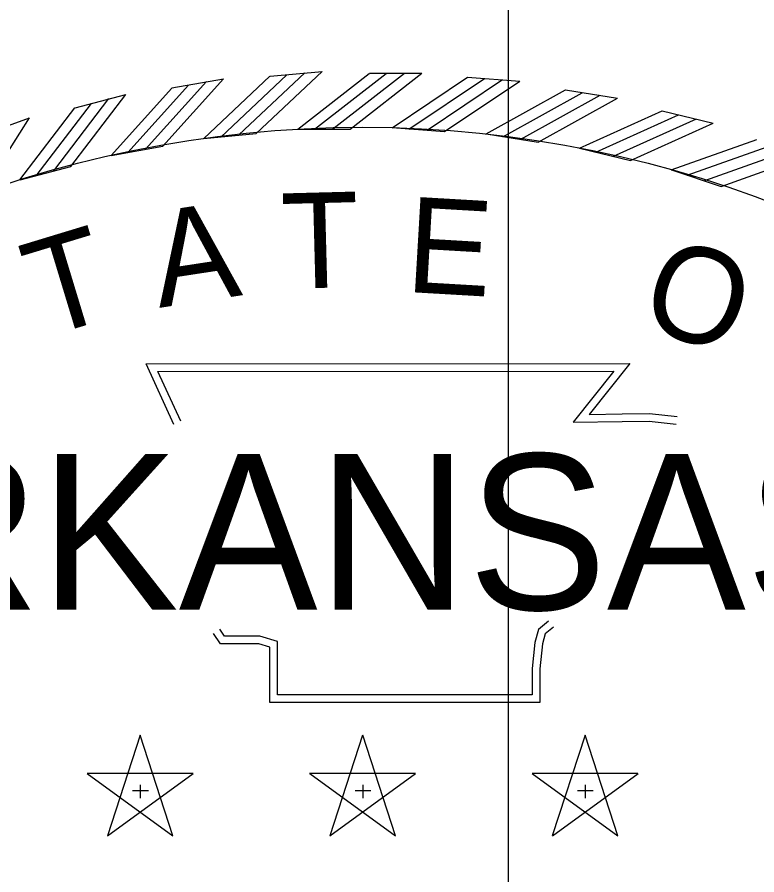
# Model space of a CAD drawing. Extents: x 18 to 14744716, y -5 to 1829144.
# Drawn here: x 17.7416 to 17.7948, y 10.9344 to 10.9961 of the extents above; entities that cross this region are included whole.
import ezdxf

# ---------------------------------------------------------------- set-up
doc = ezdxf.new("R2010")
doc.units = 0
for name, color, linetype in [('B_StampERBB', 7, 'Continuous'), ('B_StampHSS', 7, 'Continuous'), ('B_StampJSB', 7, 'Continuous'), ('B_StampSCR', 7, 'Continuous'), ('B_StampSFH', 7, 'Continuous'), ('R_No Plot', 7, 'Continuous')]:
    doc.layers.add(name, color=color, linetype=linetype)

msp = doc.modelspace()

# ---------------------------------------------------------------- linework, layer by layer
at = {"layer": 'B_StampERBB'}
for p, q in [((17.759782, 10.99184), (17.763536, 10.992186)), ((17.766921, 10.99205), (17.770691, 10.99205)), ((17.752726, 10.990997), (17.756438, 10.991651)), ((17.773983, 10.991767), (17.777742, 10.991491)), ((17.78103, 10.990852), (17.784754, 10.990266)), ((17.745763, 10.989574), (17.749409, 10.990533)), ((17.787978, 10.989358), (17.791641, 10.988467)), ((17.738942, 10.987581), (17.742496, 10.988838)), ((17.755027, 10.987373), (17.75879, 10.98772)), ((17.761776, 10.988038), (17.765555, 10.988038)), ((17.768557, 10.988144), (17.772326, 10.987867)), ((17.775324, 10.987689), (17.779057, 10.987102)), ((17.748356, 10.986153), (17.752077, 10.986809)), ((17.78203, 10.986678), (17.785702, 10.985784)), ((17.741808, 10.984385), (17.745463, 10.985347)), ((17.78863, 10.985115), (17.792215, 10.983921)), ((17.750447, 10.944483), (17.748088, 10.937247)), ((17.752797, 10.937251), (17.750452, 10.944492)), ((17.766438, 10.944483), (17.764079, 10.937247)), ((17.768788, 10.937251), (17.766443, 10.944492)), ((17.782429, 10.944483), (17.78007, 10.937247)), ((17.784779, 10.937251), (17.782434, 10.944492)), ((17.754249, 10.941721), (17.746638, 10.941728)), ((17.746645, 10.941721), (17.752798, 10.937242)), ((17.748097, 10.937251), (17.754258, 10.941719)), ((17.77024, 10.941721), (17.762629, 10.941728)), ((17.762636, 10.941721), (17.768789, 10.937242)), ((17.764088, 10.937251), (17.770249, 10.941719)), ((17.786231, 10.941721), (17.77862, 10.941728)), ((17.778627, 10.941721), (17.78478, 10.937242)), ((17.780079, 10.937251), (17.786241, 10.941719)), ((17.750454, 10.940912), (17.750454, 10.939957)), ((17.766445, 10.940912), (17.766445, 10.939957)), ((17.782436, 10.940912), (17.782436, 10.939957)), ((17.749905, 10.940505), (17.751036, 10.940505)), ((17.765896, 10.940505), (17.767027, 10.940505)), ((17.781887, 10.940505), (17.783018, 10.940505))]:
    msp.add_line(p, q, dxfattribs=at)
for points in [[(17.757534, 10.987618), (17.762288, 10.992085)], [(17.758785, 10.987722), (17.763539, 10.992189)], [(17.761772, 10.988035), (17.766915, 10.992046)], [(17.762985, 10.988024), (17.768129, 10.992035)], [(17.764295, 10.988053), (17.769438, 10.992064)], [(17.765551, 10.988041), (17.770694, 10.992053)], [(17.750833, 10.986604), (17.755202, 10.991448)], [(17.752072, 10.986811), (17.756441, 10.991655)], [(17.755023, 10.987369), (17.759777, 10.991836)], [(17.756232, 10.987469), (17.760986, 10.991936)], [(17.768553, 10.988141), (17.773977, 10.991764)], [(17.769762, 10.988041), (17.775186, 10.991664)], [(17.77107, 10.987973), (17.776494, 10.991597)], [(17.772322, 10.98787), (17.777746, 10.991493)], [(17.748352, 10.986148), (17.752721, 10.990992)], [(17.749549, 10.986348), (17.753918, 10.991192)], [(17.775319, 10.987687), (17.781024, 10.99085)], [(17.74424, 10.98504), (17.748194, 10.990228)], [(17.745458, 10.985348), (17.749412, 10.990536)], [(17.776516, 10.987487), (17.782221, 10.99065)], [(17.777814, 10.987312), (17.783519, 10.990475)], [(17.779053, 10.987105), (17.784758, 10.990268)], [(17.741805, 10.984381), (17.745759, 10.989569)], [(17.742981, 10.984679), (17.746935, 10.989867)], [(17.782025, 10.986675), (17.787972, 10.989356)], [(17.783201, 10.986377), (17.789148, 10.989058)], [(17.738986, 10.983344), (17.742498, 10.988841)], [(17.78448, 10.986096), (17.790427, 10.988777)], [(17.785698, 10.985787), (17.791645, 10.988468)], [(17.788624, 10.985113), (17.794772, 10.987294)], [(17.789772, 10.984719), (17.79592, 10.9869)], [(17.791024, 10.984333), (17.797171, 10.986514)], [(17.792211, 10.983925), (17.798359, 10.986106)], [(17.752875, 10.966818), (17.750865, 10.97117), (17.785635, 10.97119), (17.78273, 10.96754), (17.785092, 10.967571), (17.787065, 10.967597), (17.789037, 10.967382)], [(17.753375, 10.967049), (17.751726, 10.97062), (17.784493, 10.970639), (17.781576, 10.966974), (17.785099, 10.96702), (17.787039, 10.967045), (17.788977, 10.966834)], [(17.779808, 10.952675), (17.779078, 10.95208), (17.778824, 10.951147), (17.778619, 10.949271), (17.778619, 10.947388), (17.760311, 10.947388), (17.760311, 10.950082), (17.760311, 10.951211), (17.759055, 10.951594), (17.756509, 10.951594), (17.756182, 10.952094)], [(17.780156, 10.952247), (17.779563, 10.951765), (17.779366, 10.951044), (17.77917, 10.949241), (17.77917, 10.946838), (17.75976, 10.946838), (17.75976, 10.950082), (17.75976, 10.950803), (17.758973, 10.951044), (17.756212, 10.951044), (17.755721, 10.951792)]]:
    msp.add_lwpolyline(points, dxfattribs=at)
at = {"layer": 'B_StampHSS'}
for p, q in [((17.759782, 10.99184), (17.763536, 10.992186)), ((17.766921, 10.99205), (17.770691, 10.99205)), ((17.752726, 10.990997), (17.756438, 10.991651)), ((17.773983, 10.991767), (17.777742, 10.991491)), ((17.78103, 10.990852), (17.784754, 10.990266)), ((17.745763, 10.989574), (17.749409, 10.990533)), ((17.787978, 10.989358), (17.791641, 10.988467)), ((17.738942, 10.987581), (17.742496, 10.988838)), ((17.755027, 10.987373), (17.75879, 10.98772)), ((17.761776, 10.988038), (17.765555, 10.988038)), ((17.768557, 10.988144), (17.772326, 10.987867)), ((17.775324, 10.987689), (17.779057, 10.987102)), ((17.748356, 10.986153), (17.752077, 10.986809)), ((17.78203, 10.986678), (17.785702, 10.985784)), ((17.741808, 10.984385), (17.745463, 10.985347)), ((17.78863, 10.985115), (17.792215, 10.983921)), ((17.750447, 10.944483), (17.748088, 10.937247)), ((17.752797, 10.937251), (17.750452, 10.944492)), ((17.766438, 10.944483), (17.764079, 10.937247)), ((17.768788, 10.937251), (17.766443, 10.944492)), ((17.782429, 10.944483), (17.78007, 10.937247)), ((17.784779, 10.937251), (17.782434, 10.944492)), ((17.754249, 10.941721), (17.746638, 10.941728)), ((17.746645, 10.941721), (17.752798, 10.937242)), ((17.748097, 10.937251), (17.754258, 10.941719)), ((17.77024, 10.941721), (17.762629, 10.941728)), ((17.762636, 10.941721), (17.768789, 10.937242)), ((17.764088, 10.937251), (17.770249, 10.941719)), ((17.786231, 10.941721), (17.77862, 10.941728)), ((17.778627, 10.941721), (17.78478, 10.937242)), ((17.780079, 10.937251), (17.786241, 10.941719)), ((17.750454, 10.940912), (17.750454, 10.939957)), ((17.766445, 10.940912), (17.766445, 10.939957)), ((17.782436, 10.940912), (17.782436, 10.939957)), ((17.749905, 10.940505), (17.751036, 10.940505)), ((17.765896, 10.940505), (17.767027, 10.940505)), ((17.781887, 10.940505), (17.783018, 10.940505))]:
    msp.add_line(p, q, dxfattribs=at)
for points in [[(17.757534, 10.987618), (17.762288, 10.992085)], [(17.758785, 10.987722), (17.763539, 10.992189)], [(17.761772, 10.988035), (17.766915, 10.992046)], [(17.762985, 10.988024), (17.768129, 10.992035)], [(17.764295, 10.988053), (17.769438, 10.992064)], [(17.765551, 10.988041), (17.770694, 10.992053)], [(17.750833, 10.986604), (17.755202, 10.991448)], [(17.752072, 10.986811), (17.756441, 10.991655)], [(17.755023, 10.987369), (17.759777, 10.991836)], [(17.756232, 10.987469), (17.760986, 10.991936)], [(17.768553, 10.988141), (17.773977, 10.991764)], [(17.769762, 10.988041), (17.775186, 10.991664)], [(17.77107, 10.987973), (17.776494, 10.991597)], [(17.772322, 10.98787), (17.777746, 10.991493)], [(17.748352, 10.986148), (17.752721, 10.990992)], [(17.749549, 10.986348), (17.753918, 10.991192)], [(17.775319, 10.987687), (17.781024, 10.99085)], [(17.74424, 10.98504), (17.748194, 10.990228)], [(17.745458, 10.985348), (17.749412, 10.990536)], [(17.776516, 10.987487), (17.782221, 10.99065)], [(17.777814, 10.987312), (17.783519, 10.990475)], [(17.779053, 10.987105), (17.784758, 10.990268)], [(17.741805, 10.984381), (17.745759, 10.989569)], [(17.742981, 10.984679), (17.746935, 10.989867)], [(17.782025, 10.986675), (17.787972, 10.989356)], [(17.783201, 10.986377), (17.789148, 10.989058)], [(17.738986, 10.983344), (17.742498, 10.988841)], [(17.78448, 10.986096), (17.790427, 10.988777)], [(17.785698, 10.985787), (17.791645, 10.988468)], [(17.788624, 10.985113), (17.794772, 10.987294)], [(17.789772, 10.984719), (17.79592, 10.9869)], [(17.791024, 10.984333), (17.797171, 10.986514)], [(17.792211, 10.983925), (17.798359, 10.986106)], [(17.752875, 10.966818), (17.750865, 10.97117), (17.785635, 10.97119), (17.78273, 10.96754), (17.785092, 10.967571), (17.787065, 10.967597), (17.789037, 10.967382)], [(17.753375, 10.967049), (17.751726, 10.97062), (17.784493, 10.970639), (17.781576, 10.966974), (17.785099, 10.96702), (17.787039, 10.967045), (17.788977, 10.966834)], [(17.779808, 10.952675), (17.779078, 10.95208), (17.778824, 10.951147), (17.778619, 10.949271), (17.778619, 10.947388), (17.760311, 10.947388), (17.760311, 10.950082), (17.760311, 10.951211), (17.759055, 10.951594), (17.756509, 10.951594), (17.756182, 10.952094)], [(17.780156, 10.952247), (17.779563, 10.951765), (17.779366, 10.951044), (17.77917, 10.949241), (17.77917, 10.946838), (17.75976, 10.946838), (17.75976, 10.950082), (17.75976, 10.950803), (17.758973, 10.951044), (17.756212, 10.951044), (17.755721, 10.951792)]]:
    msp.add_lwpolyline(points, dxfattribs=at)
at = {"layer": 'B_StampJSB'}
for p, q in [((17.759782, 10.99184), (17.763536, 10.992186)), ((17.766921, 10.99205), (17.770691, 10.99205)), ((17.752726, 10.990997), (17.756438, 10.991651)), ((17.773983, 10.991767), (17.777742, 10.991491)), ((17.78103, 10.990852), (17.784754, 10.990266)), ((17.745763, 10.989574), (17.749409, 10.990533)), ((17.787978, 10.989358), (17.791641, 10.988467)), ((17.738942, 10.987581), (17.742496, 10.988838)), ((17.755027, 10.987373), (17.75879, 10.98772)), ((17.761776, 10.988038), (17.765555, 10.988038)), ((17.768557, 10.988144), (17.772326, 10.987867)), ((17.775324, 10.987689), (17.779057, 10.987102)), ((17.748356, 10.986153), (17.752077, 10.986809)), ((17.78203, 10.986678), (17.785702, 10.985784)), ((17.741808, 10.984385), (17.745463, 10.985347)), ((17.78863, 10.985115), (17.792215, 10.983921)), ((17.750447, 10.944483), (17.748088, 10.937247)), ((17.752797, 10.937251), (17.750452, 10.944492)), ((17.766438, 10.944483), (17.764079, 10.937247)), ((17.768788, 10.937251), (17.766443, 10.944492)), ((17.782429, 10.944483), (17.78007, 10.937247)), ((17.784779, 10.937251), (17.782434, 10.944492)), ((17.754249, 10.941721), (17.746638, 10.941728)), ((17.746645, 10.941721), (17.752798, 10.937242)), ((17.748097, 10.937251), (17.754258, 10.941719)), ((17.77024, 10.941721), (17.762629, 10.941728)), ((17.762636, 10.941721), (17.768789, 10.937242)), ((17.764088, 10.937251), (17.770249, 10.941719)), ((17.786231, 10.941721), (17.77862, 10.941728)), ((17.778627, 10.941721), (17.78478, 10.937242)), ((17.780079, 10.937251), (17.786241, 10.941719)), ((17.750454, 10.940912), (17.750454, 10.939957)), ((17.766445, 10.940912), (17.766445, 10.939957)), ((17.782436, 10.940912), (17.782436, 10.939957)), ((17.749905, 10.940505), (17.751036, 10.940505)), ((17.765896, 10.940505), (17.767027, 10.940505)), ((17.781887, 10.940505), (17.783018, 10.940505))]:
    msp.add_line(p, q, dxfattribs=at)
for points in [[(17.757534, 10.987618), (17.762288, 10.992085)], [(17.758785, 10.987722), (17.763539, 10.992189)], [(17.761772, 10.988035), (17.766915, 10.992046)], [(17.762985, 10.988024), (17.768129, 10.992035)], [(17.764295, 10.988053), (17.769438, 10.992064)], [(17.765551, 10.988041), (17.770694, 10.992053)], [(17.750833, 10.986604), (17.755202, 10.991448)], [(17.752072, 10.986811), (17.756441, 10.991655)], [(17.755023, 10.987369), (17.759777, 10.991836)], [(17.756232, 10.987469), (17.760986, 10.991936)], [(17.768553, 10.988141), (17.773977, 10.991764)], [(17.769762, 10.988041), (17.775186, 10.991664)], [(17.77107, 10.987973), (17.776494, 10.991597)], [(17.772322, 10.98787), (17.777746, 10.991493)], [(17.748352, 10.986148), (17.752721, 10.990992)], [(17.749549, 10.986348), (17.753918, 10.991192)], [(17.775319, 10.987687), (17.781024, 10.99085)], [(17.74424, 10.98504), (17.748194, 10.990228)], [(17.745458, 10.985348), (17.749412, 10.990536)], [(17.776516, 10.987487), (17.782221, 10.99065)], [(17.777814, 10.987312), (17.783519, 10.990475)], [(17.779053, 10.987105), (17.784758, 10.990268)], [(17.741805, 10.984381), (17.745759, 10.989569)], [(17.742981, 10.984679), (17.746935, 10.989867)], [(17.782025, 10.986675), (17.787972, 10.989356)], [(17.783201, 10.986377), (17.789148, 10.989058)], [(17.738986, 10.983344), (17.742498, 10.988841)], [(17.78448, 10.986096), (17.790427, 10.988777)], [(17.785698, 10.985787), (17.791645, 10.988468)], [(17.788624, 10.985113), (17.794772, 10.987294)], [(17.789772, 10.984719), (17.79592, 10.9869)], [(17.791024, 10.984333), (17.797171, 10.986514)], [(17.792211, 10.983925), (17.798359, 10.986106)], [(17.752875, 10.966818), (17.750865, 10.97117), (17.785635, 10.97119), (17.78273, 10.96754), (17.785092, 10.967571), (17.787065, 10.967597), (17.789037, 10.967382)], [(17.753375, 10.967049), (17.751726, 10.97062), (17.784493, 10.970639), (17.781576, 10.966974), (17.785099, 10.96702), (17.787039, 10.967045), (17.788977, 10.966834)], [(17.779808, 10.952675), (17.779078, 10.95208), (17.778824, 10.951147), (17.778619, 10.949271), (17.778619, 10.947388), (17.760311, 10.947388), (17.760311, 10.950082), (17.760311, 10.951211), (17.759055, 10.951594), (17.756509, 10.951594), (17.756182, 10.952094)], [(17.780156, 10.952247), (17.779563, 10.951765), (17.779366, 10.951044), (17.77917, 10.949241), (17.77917, 10.946838), (17.75976, 10.946838), (17.75976, 10.950082), (17.75976, 10.950803), (17.758973, 10.951044), (17.756212, 10.951044), (17.755721, 10.951792)]]:
    msp.add_lwpolyline(points, dxfattribs=at)
msp.add_circle((17.766447, 10.906117), 0.082054, dxfattribs=at)
at = {"layer": 'B_StampSCR'}
for p, q in [((17.759782, 10.99184), (17.763536, 10.992186)), ((17.766921, 10.99205), (17.770691, 10.99205)), ((17.752726, 10.990997), (17.756438, 10.991651)), ((17.773983, 10.991767), (17.777742, 10.991491)), ((17.78103, 10.990852), (17.784754, 10.990266)), ((17.745763, 10.989574), (17.749409, 10.990533)), ((17.787978, 10.989358), (17.791641, 10.988467)), ((17.738942, 10.987581), (17.742496, 10.988838)), ((17.755027, 10.987373), (17.75879, 10.98772)), ((17.761776, 10.988038), (17.765555, 10.988038)), ((17.768557, 10.988144), (17.772326, 10.987867)), ((17.775324, 10.987689), (17.779057, 10.987102)), ((17.748356, 10.986153), (17.752077, 10.986809)), ((17.78203, 10.986678), (17.785702, 10.985784)), ((17.741808, 10.984385), (17.745463, 10.985347)), ((17.78863, 10.985115), (17.792215, 10.983921)), ((17.750447, 10.944483), (17.748088, 10.937247)), ((17.752797, 10.937251), (17.750452, 10.944492)), ((17.766438, 10.944483), (17.764079, 10.937247)), ((17.768788, 10.937251), (17.766443, 10.944492)), ((17.782429, 10.944483), (17.78007, 10.937247)), ((17.784779, 10.937251), (17.782434, 10.944492)), ((17.754249, 10.941721), (17.746638, 10.941728)), ((17.746645, 10.941721), (17.752798, 10.937242)), ((17.748097, 10.937251), (17.754258, 10.941719)), ((17.77024, 10.941721), (17.762629, 10.941728)), ((17.762636, 10.941721), (17.768789, 10.937242)), ((17.764088, 10.937251), (17.770249, 10.941719)), ((17.786231, 10.941721), (17.77862, 10.941728)), ((17.778627, 10.941721), (17.78478, 10.937242)), ((17.780079, 10.937251), (17.786241, 10.941719)), ((17.750454, 10.940912), (17.750454, 10.939957)), ((17.766445, 10.940912), (17.766445, 10.939957)), ((17.782436, 10.940912), (17.782436, 10.939957)), ((17.749905, 10.940505), (17.751036, 10.940505)), ((17.765896, 10.940505), (17.767027, 10.940505)), ((17.781887, 10.940505), (17.783018, 10.940505))]:
    msp.add_line(p, q, dxfattribs=at)
for points in [[(17.757534, 10.987618), (17.762288, 10.992085)], [(17.758785, 10.987722), (17.763539, 10.992189)], [(17.761772, 10.988035), (17.766915, 10.992046)], [(17.762985, 10.988024), (17.768129, 10.992035)], [(17.764295, 10.988053), (17.769438, 10.992064)], [(17.765551, 10.988041), (17.770694, 10.992053)], [(17.750833, 10.986604), (17.755202, 10.991448)], [(17.752072, 10.986811), (17.756441, 10.991655)], [(17.755023, 10.987369), (17.759777, 10.991836)], [(17.756232, 10.987469), (17.760986, 10.991936)], [(17.768553, 10.988141), (17.773977, 10.991764)], [(17.769762, 10.988041), (17.775186, 10.991664)], [(17.77107, 10.987973), (17.776494, 10.991597)], [(17.772322, 10.98787), (17.777746, 10.991493)], [(17.748352, 10.986148), (17.752721, 10.990992)], [(17.749549, 10.986348), (17.753918, 10.991192)], [(17.775319, 10.987687), (17.781024, 10.99085)], [(17.74424, 10.98504), (17.748194, 10.990228)], [(17.745458, 10.985348), (17.749412, 10.990536)], [(17.776516, 10.987487), (17.782221, 10.99065)], [(17.777814, 10.987312), (17.783519, 10.990475)], [(17.779053, 10.987105), (17.784758, 10.990268)], [(17.741805, 10.984381), (17.745759, 10.989569)], [(17.742981, 10.984679), (17.746935, 10.989867)], [(17.782025, 10.986675), (17.787972, 10.989356)], [(17.783201, 10.986377), (17.789148, 10.989058)], [(17.738986, 10.983344), (17.742498, 10.988841)], [(17.78448, 10.986096), (17.790427, 10.988777)], [(17.785698, 10.985787), (17.791645, 10.988468)], [(17.788624, 10.985113), (17.794772, 10.987294)], [(17.789772, 10.984719), (17.79592, 10.9869)], [(17.791024, 10.984333), (17.797171, 10.986514)], [(17.792211, 10.983925), (17.798359, 10.986106)], [(17.752875, 10.966818), (17.750865, 10.97117), (17.785635, 10.97119), (17.78273, 10.96754), (17.785092, 10.967571), (17.787065, 10.967597), (17.789037, 10.967382)], [(17.753375, 10.967049), (17.751726, 10.97062), (17.784493, 10.970639), (17.781576, 10.966974), (17.785099, 10.96702), (17.787039, 10.967045), (17.788977, 10.966834)], [(17.779808, 10.952675), (17.779078, 10.95208), (17.778824, 10.951147), (17.778619, 10.949271), (17.778619, 10.947388), (17.760311, 10.947388), (17.760311, 10.950082), (17.760311, 10.951211), (17.759055, 10.951594), (17.756509, 10.951594), (17.756182, 10.952094)], [(17.780156, 10.952247), (17.779563, 10.951765), (17.779366, 10.951044), (17.77917, 10.949241), (17.77917, 10.946838), (17.75976, 10.946838), (17.75976, 10.950082), (17.75976, 10.950803), (17.758973, 10.951044), (17.756212, 10.951044), (17.755721, 10.951792)]]:
    msp.add_lwpolyline(points, dxfattribs=at)
at = {"layer": 'B_StampSFH'}
for p, q in [((17.759782, 10.99184), (17.763536, 10.992186)), ((17.766921, 10.99205), (17.770691, 10.99205)), ((17.752726, 10.990997), (17.756438, 10.991651)), ((17.773983, 10.991767), (17.777742, 10.991491)), ((17.78103, 10.990852), (17.784754, 10.990266)), ((17.745763, 10.989574), (17.749409, 10.990533)), ((17.787978, 10.989358), (17.791641, 10.988467)), ((17.738942, 10.987581), (17.742496, 10.988838)), ((17.755027, 10.987373), (17.75879, 10.98772)), ((17.761776, 10.988038), (17.765555, 10.988038)), ((17.768557, 10.988144), (17.772326, 10.987867)), ((17.775324, 10.987689), (17.779057, 10.987102)), ((17.748356, 10.986153), (17.752077, 10.986809)), ((17.78203, 10.986678), (17.785702, 10.985784)), ((17.741808, 10.984385), (17.745463, 10.985347)), ((17.78863, 10.985115), (17.792215, 10.983921)), ((17.750447, 10.944483), (17.748088, 10.937247)), ((17.752797, 10.937251), (17.750452, 10.944492)), ((17.766438, 10.944483), (17.764079, 10.937247)), ((17.768788, 10.937251), (17.766443, 10.944492)), ((17.782429, 10.944483), (17.78007, 10.937247)), ((17.784779, 10.937251), (17.782434, 10.944492)), ((17.754249, 10.941721), (17.746638, 10.941728)), ((17.746645, 10.941721), (17.752798, 10.937242)), ((17.748097, 10.937251), (17.754258, 10.941719)), ((17.77024, 10.941721), (17.762629, 10.941728)), ((17.762636, 10.941721), (17.768789, 10.937242)), ((17.764088, 10.937251), (17.770249, 10.941719)), ((17.786231, 10.941721), (17.77862, 10.941728)), ((17.778627, 10.941721), (17.78478, 10.937242)), ((17.780079, 10.937251), (17.786241, 10.941719)), ((17.750454, 10.940912), (17.750454, 10.939957)), ((17.766445, 10.940912), (17.766445, 10.939957)), ((17.782436, 10.940912), (17.782436, 10.939957)), ((17.749905, 10.940505), (17.751036, 10.940505)), ((17.765896, 10.940505), (17.767027, 10.940505)), ((17.781887, 10.940505), (17.783018, 10.940505))]:
    msp.add_line(p, q, dxfattribs=at)
for points in [[(17.757534, 10.987618), (17.762288, 10.992085)], [(17.758785, 10.987722), (17.763539, 10.992189)], [(17.761772, 10.988035), (17.766915, 10.992046)], [(17.762985, 10.988024), (17.768129, 10.992035)], [(17.764295, 10.988053), (17.769438, 10.992064)], [(17.765551, 10.988041), (17.770694, 10.992053)], [(17.750833, 10.986604), (17.755202, 10.991448)], [(17.752072, 10.986811), (17.756441, 10.991655)], [(17.755023, 10.987369), (17.759777, 10.991836)], [(17.756232, 10.987469), (17.760986, 10.991936)], [(17.768553, 10.988141), (17.773977, 10.991764)], [(17.769762, 10.988041), (17.775186, 10.991664)], [(17.77107, 10.987973), (17.776494, 10.991597)], [(17.772322, 10.98787), (17.777746, 10.991493)], [(17.748352, 10.986148), (17.752721, 10.990992)], [(17.749549, 10.986348), (17.753918, 10.991192)], [(17.775319, 10.987687), (17.781024, 10.99085)], [(17.74424, 10.98504), (17.748194, 10.990228)], [(17.745458, 10.985348), (17.749412, 10.990536)], [(17.776516, 10.987487), (17.782221, 10.99065)], [(17.777814, 10.987312), (17.783519, 10.990475)], [(17.779053, 10.987105), (17.784758, 10.990268)], [(17.741805, 10.984381), (17.745759, 10.989569)], [(17.742981, 10.984679), (17.746935, 10.989867)], [(17.782025, 10.986675), (17.787972, 10.989356)], [(17.783201, 10.986377), (17.789148, 10.989058)], [(17.738986, 10.983344), (17.742498, 10.988841)], [(17.78448, 10.986096), (17.790427, 10.988777)], [(17.785698, 10.985787), (17.791645, 10.988468)], [(17.788624, 10.985113), (17.794772, 10.987294)], [(17.789772, 10.984719), (17.79592, 10.9869)], [(17.791024, 10.984333), (17.797171, 10.986514)], [(17.792211, 10.983925), (17.798359, 10.986106)], [(17.752875, 10.966818), (17.750865, 10.97117), (17.785635, 10.97119), (17.78273, 10.96754), (17.785092, 10.967571), (17.787065, 10.967597), (17.789037, 10.967382)], [(17.753375, 10.967049), (17.751726, 10.97062), (17.784493, 10.970639), (17.781576, 10.966974), (17.785099, 10.96702), (17.787039, 10.967045), (17.788977, 10.966834)], [(17.779808, 10.952675), (17.779078, 10.95208), (17.778824, 10.951147), (17.778619, 10.949271), (17.778619, 10.947388), (17.760311, 10.947388), (17.760311, 10.950082), (17.760311, 10.951211), (17.759055, 10.951594), (17.756509, 10.951594), (17.756182, 10.952094)], [(17.780156, 10.952247), (17.779563, 10.951765), (17.779366, 10.951044), (17.77917, 10.949241), (17.77917, 10.946838), (17.75976, 10.946838), (17.75976, 10.950082), (17.75976, 10.950803), (17.758973, 10.951044), (17.756212, 10.951044), (17.755721, 10.951792)]]:
    msp.add_lwpolyline(points, dxfattribs=at)
at = {"layer": 'R_No Plot'}
msp.add_lwpolyline([(17.776919, 16.627613), (51.776919, 16.627613), (51.776919, -5.372387), (17.776919, -5.372387)], close=True, dxfattribs=at)

# ---------------------------------------------------------------- texts
at = {"layer": 'B_StampERBB'}
for s, rotation, p in [('T', 1.47887, (17.760672, 10.976553)), ('E', 356.67203, (17.769449, 10.976345)), ('A', 8.67877, (17.751815, 10.975189)), ('T', 16.90148, (17.743487, 10.973014)), ('O', 341.2218, (17.786102, 10.973993))]:
    msp.add_text(s, height=0.006859, rotation=rotation, dxfattribs=at).set_placement(p)
msp.add_text('ARKANSAS', height=0.0111938, dxfattribs=at).set_placement((17.722443, 10.953498))
at = {"layer": 'B_StampHSS'}
for s, rotation, p in [('T', 1.47887, (17.760672, 10.976553)), ('E', 356.67203, (17.769449, 10.976345)), ('A', 8.67877, (17.751815, 10.975189)), ('T', 16.90148, (17.743487, 10.973014)), ('O', 341.2218, (17.786102, 10.973993))]:
    msp.add_text(s, height=0.006859, rotation=rotation, dxfattribs=at).set_placement(p)
msp.add_text('ARKANSAS', height=0.0111938, dxfattribs=at).set_placement((17.722443, 10.953498))
at = {"layer": 'B_StampJSB'}
for s, rotation, p in [('T', 1.47887, (17.760672, 10.976553)), ('E', 356.67203, (17.769449, 10.976345)), ('A', 8.67877, (17.751815, 10.975189)), ('T', 16.90148, (17.743487, 10.973014)), ('O', 341.2218, (17.786102, 10.973993))]:
    msp.add_text(s, height=0.006859, rotation=rotation, dxfattribs=at).set_placement(p)
msp.add_text('ARKANSAS', height=0.0111938, dxfattribs=at).set_placement((17.722443, 10.953498))
at = {"layer": 'B_StampSCR'}
for s, rotation, p in [('T', 1.47887, (17.760672, 10.976553)), ('E', 356.67203, (17.769449, 10.976345)), ('A', 8.67877, (17.751815, 10.975189)), ('T', 16.90148, (17.743487, 10.973014)), ('O', 341.2218, (17.786102, 10.973993))]:
    msp.add_text(s, height=0.006859, rotation=rotation, dxfattribs=at).set_placement(p)
msp.add_text('ARKANSAS', height=0.0111938, dxfattribs=at).set_placement((17.722443, 10.953498))
at = {"layer": 'B_StampSFH'}
for s, rotation, p in [('T', 1.47887, (17.760672, 10.976553)), ('E', 356.67203, (17.769449, 10.976345)), ('A', 8.67877, (17.751815, 10.975189)), ('T', 16.90148, (17.743487, 10.973014)), ('O', 341.2218, (17.786102, 10.973993))]:
    msp.add_text(s, height=0.006859, rotation=rotation, dxfattribs=at).set_placement(p)
msp.add_text('ARKANSAS', height=0.0111938, dxfattribs=at).set_placement((17.722443, 10.953498))

doc.saveas('drawing.dxf')
